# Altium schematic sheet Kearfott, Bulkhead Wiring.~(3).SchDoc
size B; Organization: Monterey Bay Aquarium Research Institute; Address1: 7700 Sandholdt Rd; Address2: Moss Landing, CA 95039-9644; CompanyName: MBARI
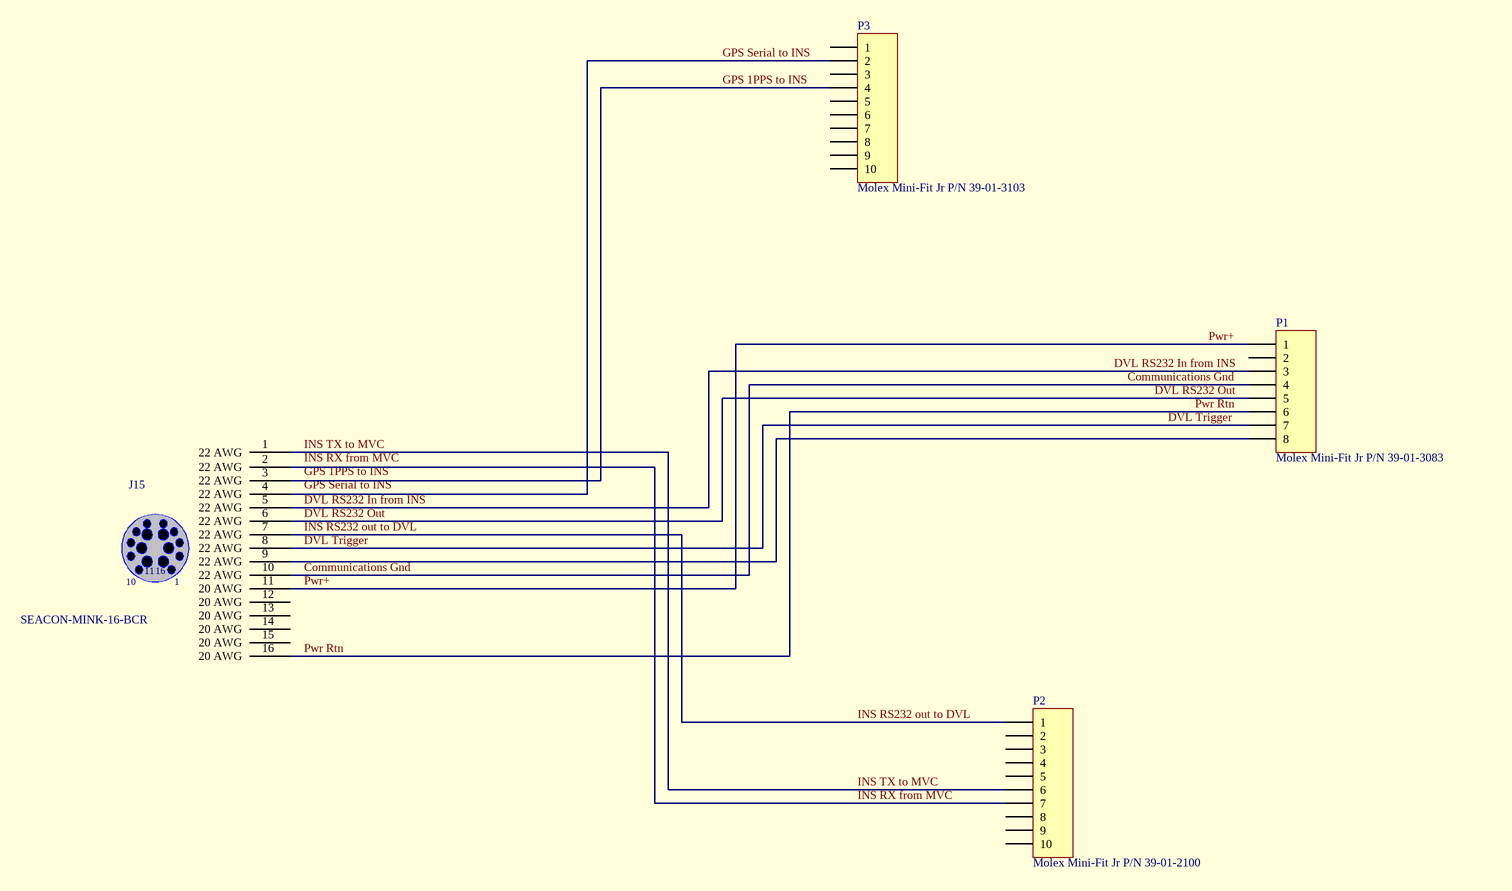
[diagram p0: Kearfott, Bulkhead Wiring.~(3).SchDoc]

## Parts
J15  SEACON-MINK-16-BCR
P1  Molex Mini-Fit Jr P/N 39-01-3083  [HDR1X8]
P2  Molex Mini-Fit Jr P/N 39-01-2100  [HDR1X10]
P3  Molex Mini-Fit Jr P/N 39-01-3103  [HDR1X10]

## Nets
Communications Gnd: J15.10(22_AWG) P1.4
DVL RS232 In from INS: J15.5(22_AWG) P1.3
DVL RS232 Out: J15.6(22_AWG) P1.5
DVL Trigger: J15.8(22_AWG) P1.7
GPS 1PPS to INS: J15.3(22_AWG) P3.4
GPS Serial to INS: J15.4(22_AWG) P3.2
INS RS232 out to DVL: J15.7(22_AWG) P2.1
INS RX from MVC: J15.2(22_AWG) P2.7
INS TX to MVC: J15.1(22_AWG) P2.6
Pwr Rtn: J15.16(20_AWG) P1.6
Pwr+: J15.11(20_AWG) P1.1
NetJ15_9: J15.9(22_AWG) P1.8

Not connected (* = marked no-connect by the designer): J15 12(20_AWG) 13(20_AWG) 14(20_AWG) 15(20_AWG); P1 2; P2 2 3 4 5 8 9 10; P3 1 3 5 6 7 8 9 10

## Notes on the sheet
- Labels drawn without touching a wire or pin: GPS 1PPS to INS, GPS Serial to INS, INS RX from MVC

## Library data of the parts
J15 = SEACON-MINK-16-FCR: Seacon MINK-16 FCR
P1 = Header 8: Header, 8-Pin
P2 P3 = Header 10: Header, 10-Pin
